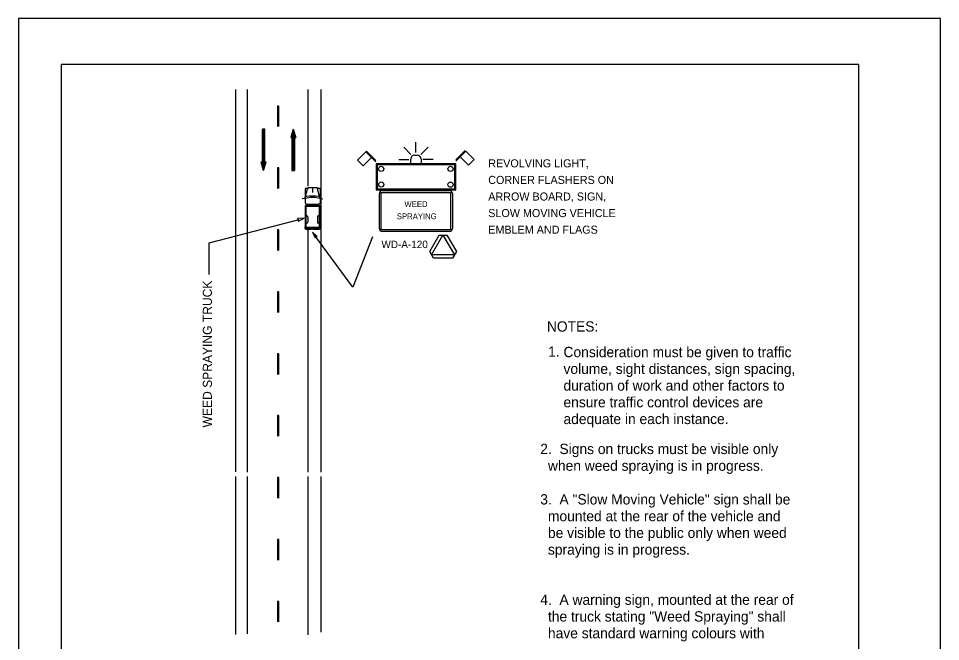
# Model space of a CAD drawing. Extents: x 1578 to 1794, y 169 to 448.
# Drawn here: x 1578.5 to 1794.5, y 301.9 to 448 of the extents above; entities that cross this region are included whole.
import ezdxf

# ---------------------------------------------------------------- set-up
doc = ezdxf.new("R2010")
doc.units = 0
for name, color, linetype in [('Level 1', 7, 'Continuous'), ('Level 10', 7, 'Continuous'), ('Level 2', 7, 'Continuous'), ('Level 44', 7, 'Continuous'), ('Level 60', 7, 'Continuous')]:
    doc.layers.add(name, color=color, linetype=linetype)

msp = doc.modelspace()

# ---------------------------------------------------------------- linework, layer by layer
at = {"layer": 'Level 1'}
for p, q in [((1646.51, 408.35), (1648.24, 408.35)), ((1647.37, 408.35), (1647.37, 407.24)), ((1645.6, 407.91), (1645.6, 404.82)), ((1645.66, 406.03), (1646.21, 408.09)), ((1645.9, 408.22), (1646.26, 408.22)), ((1648.49, 408.22), (1648.85, 408.22)), ((1649.07, 406.03), (1648.53, 408.09)), ((1649.14, 407.91), (1649.14, 404.82)), ((1645.6, 405.81), (1644.96, 405.74)), ((1645.6, 405.8), (1644.96, 405.72)), ((1645.6, 405.78), (1644.96, 405.7)), ((1645.6, 405.8), (1645.66, 406.03)), ((1645.6, 405.41), (1645.6, 405.41)), ((1645.6, 403.97), (1645.6, 399.15)), ((1645.82, 403.97), (1645.82, 399.15)), ((1645.9, 404.52), (1648.85, 404.52)), ((1645.9, 404.27), (1648.85, 404.27)), ((1645.9, 404.05), (1648.85, 404.05)), ((1648.92, 403.97), (1648.92, 399.15)), ((1649.14, 405.8), (1649.08, 406.03)), ((1649.14, 405.81), (1649.79, 405.74)), ((1649.14, 405.8), (1649.79, 405.72)), ((1649.14, 405.78), (1649.79, 405.7)), ((1649.14, 403.97), (1649.14, 399.15)), ((1645.82, 401.76), (1646.02, 401.76)), ((1648.92, 401.76), (1648.72, 401.76)), ((1645.82, 400.02), (1646.02, 400.02)), ((1646.26, 401.53), (1646.26, 400.25)), ((1648.49, 401.53), (1648.49, 400.25)), ((1648.92, 400.02), (1648.72, 400.02)), ((1645.54, 399.15), (1645.54, 398.89)), ((1645.83, 398.6), (1647.15, 398.6)), ((1645.9, 399.08), (1648.85, 399.08)), ((1645.9, 398.86), (1648.85, 398.86)), ((1647.6, 398.6), (1648.92, 398.6)), ((1649.21, 399.15), (1649.21, 398.89)), ((1674.8, 393.42), (1677, 397.23)), ((1675.26, 392.62), (1677.92, 397.23)), ((1677, 397.23), (1678.85, 397.23)), ((1677.92, 397.23), (1680.59, 392.62)), ((1678.85, 397.23), (1681.05, 393.42)), ((1675.72, 391.82), (1674.8, 393.42)), ((1681.05, 393.42), (1680.13, 391.82)), ((1680.59, 392.62), (1675.26, 392.62)), ((1680.13, 391.82), (1675.72, 391.82))]:
    msp.add_line(p, q, dxfattribs=at)
for centre, radius, start, end in [((1646.51, 408.05), 0.297, 90, 172.554), ((1648.24, 408.05), 0.297, 7.446, 90), ((1645.9, 407.92), 0.297, 90, 180), ((1645.95, 405.96), 0.297, 101.1133, 164.8989), ((1647.37, 398.73), 7.66, 78.8894, 101.1106), ((1648.85, 407.92), 0.297, 0, 90), ((1648.79, 405.96), 0.297, 14.8586, 78.8916), ((1647.37, 398.73), 7.29, 75.9432, 104.0544), ((1645.9, 404.82), 0.297, 180, 270), ((1645.9, 403.97), 0.297, 90, 180), ((1645.9, 403.97), 0.0766, 90, 180), ((1648.85, 404.82), 0.297, 270, 360), ((1648.85, 403.97), 0.297, 360, 90), ((1648.85, 403.97), 0.0766, 360, 90), ((1645.9, 399.15), 0.297, 180, 270), ((1645.9, 399.15), 0.0766, 180, 270), ((1648.85, 399.15), 0.297, 270, 360), ((1648.85, 399.15), 0.0766, 270, 360)]:
    msp.add_arc(centre, radius, start, end, dxfattribs=at)
at = {"layer": 'Level 10'}
for p, q in [((1629.33, 431.35), (1629.33, 341.73)), ((1632.06, 431.35), (1632.06, 341.68)), ((1646.28, 431.35), (1646.28, 408.73)), ((1649.3, 431.35), (1649.3, 341.62)), ((1635.62, 414.3), (1635.62, 422.05)), ((1636.2, 422.05), (1635.62, 422.05)), ((1635.62, 413.34), (1635.62, 422.05)), ((1635.69, 413.1), (1635.69, 422.05)), ((1635.77, 412.85), (1635.77, 422.05)), ((1635.84, 412.61), (1635.84, 422.05)), ((1635.91, 412.37), (1635.91, 422.05)), ((1635.98, 412.61), (1635.98, 422.05)), ((1636.06, 412.85), (1636.06, 422.05)), ((1636.13, 413.1), (1636.13, 422.05)), ((1636.2, 414.3), (1636.2, 422.05)), ((1636.2, 413.34), (1636.2, 422.05)), ((1642.84, 422.06), (1642.26, 420.13)), ((1642.62, 421.34), (1642.62, 412.39)), ((1642.7, 421.58), (1642.7, 412.39)), ((1642.77, 421.82), (1642.77, 412.39)), ((1642.84, 422.06), (1642.84, 412.39)), ((1642.84, 422.06), (1643.42, 420.13)), ((1642.91, 421.82), (1642.91, 412.39)), ((1642.99, 421.58), (1642.99, 412.39)), ((1643.06, 421.34), (1643.06, 412.39)), ((1642.26, 420.13), (1642.55, 420.13)), ((1642.33, 420.37), (1642.33, 420.13)), ((1642.41, 420.61), (1642.41, 420.13)), ((1642.48, 420.85), (1642.48, 420.13)), ((1642.55, 421.09), (1642.55, 412.39)), ((1642.55, 420.13), (1642.55, 412.39)), ((1643.13, 421.09), (1643.13, 412.39)), ((1643.13, 420.13), (1643.13, 412.39)), ((1643.13, 420.13), (1643.42, 420.13)), ((1643.2, 420.85), (1643.2, 420.13)), ((1643.28, 420.61), (1643.28, 420.13)), ((1643.35, 420.37), (1643.35, 420.13)), ((1660.03, 416.91), (1659.88, 416.75)), ((1670.42, 416.13), (1668.74, 417.81)), ((1671.58, 416.61), (1671.58, 418.99)), ((1672.74, 416.13), (1674.42, 417.81)), ((1681.93, 415.59), (1683.24, 416.9)), ((1683.24, 416.9), (1685.21, 414.93)), ((1659.88, 416.75), (1657.91, 414.78)), ((1657.91, 414.78), (1659.22, 413.47)), ((1659.22, 413.47), (1661.19, 415.44)), ((1661.19, 415.44), (1659.88, 416.75)), ((1661.19, 415.44), (1661.19, 415.44)), ((1667.56, 414.97), (1669.94, 414.97)), ((1670.37, 413.96), (1670.37, 415.05)), ((1671.3, 415.98), (1671.86, 415.98)), ((1671.56, 415.98), (1671.58, 415.98)), ((1672.79, 415.05), (1672.79, 413.96)), ((1675.6, 414.97), (1673.23, 414.97)), ((1683.9, 413.62), (1681.93, 415.59)), ((1681.93, 415.59), (1681.93, 415.59)), ((1685.21, 414.93), (1683.9, 413.62)), ((1635.91, 412.37), (1635.33, 414.3)), ((1635.62, 414.3), (1635.33, 414.3)), ((1635.4, 414.06), (1635.4, 414.3)), ((1635.48, 413.82), (1635.48, 414.3)), ((1635.55, 413.58), (1635.55, 414.3)), ((1635.91, 412.37), (1636.49, 414.3)), ((1636.49, 414.3), (1636.2, 414.3)), ((1636.28, 413.58), (1636.28, 414.3)), ((1636.35, 413.82), (1636.35, 414.3)), ((1636.42, 414.06), (1636.42, 414.3)), ((1672.79, 413.96), (1670.37, 413.96)), ((1642.55, 412.39), (1643.13, 412.39)), ((1663.02, 398.8), (1663.02, 406.97)), ((1663.71, 407.67), (1679.42, 407.67)), ((1671.57, 407.67), (1671.57, 407.67)), ((1680.12, 406.97), (1680.12, 398.8)), ((1645.54, 399.15), (1645.6, 399.15)), ((1646.28, 398.6), (1646.28, 341.62)), ((1649.21, 399.15), (1649.14, 399.15)), ((1679.42, 398.1), (1663.71, 398.1)), ((1629.33, 340.65), (1629.33, 303.63)), ((1632.06, 340.65), (1632.06, 303.75)), ((1646.28, 340.65), (1646.28, 303.5)), ((1649.3, 340.65), (1649.3, 304.12))]:
    msp.add_line(p, q, dxfattribs=at)
msp.add_lwpolyline([(1663.45, 407.2), (1679.67, 407.2), (1679.67, 398.46), (1663.45, 398.46)], close=True, dxfattribs=at)
for points in [[(1623.17, 387.99), (1623.17, 395.39), (1644.23, 400.91)], [(1661.42, 396.82), (1656.81, 385), (1647.89, 397.12)]]:
    msp.add_lwpolyline(points, dxfattribs=at)
for centre, radius in [((1663.46, 412.76), 0.609), ((1679.7, 412.76), 0.609), ((1663.46, 409.09), 0.609), ((1679.7, 409.05), 0.609), ((1647.37, 398.64), 0.0581)]:
    msp.add_circle(centre, radius, dxfattribs=at)
for centre, radius, start, end in [((1671.3, 415.05), 0.929, 90, 180), ((1671.86, 415.05), 0.929, 0, 90), ((1663.71, 406.97), 0.697, 90, 180), ((1679.42, 406.97), 0.697, 0, 90), ((1646.02, 401.53), 0.232, 0, 90), ((1648.72, 401.53), 0.232, 90, 180), ((1646.02, 400.25), 0.232, 270, 0), ((1648.72, 400.25), 0.232, 180, 270), ((1645.83, 398.89), 0.29, 180, 270), ((1647.37, 398.64), 0.174, 29.9957, 149.9771), ((1648.92, 398.89), 0.29, 270, 0), ((1663.71, 398.8), 0.697, 180, 270), ((1679.42, 398.8), 0.697, 270, 0)]:
    msp.add_arc(centre, radius, start, end, dxfattribs=at)
at = {"layer": 'Level 2'}
for p, q in [((1639.15, 427.49), (1639.15, 422.65)), ((1639.44, 427.49), (1639.15, 427.49)), ((1639.44, 422.65), (1639.44, 427.49)), ((1639.15, 412.97), (1639.15, 408.13)), ((1639.44, 412.97), (1639.15, 412.97)), ((1639.44, 408.13), (1639.44, 412.97)), ((1639.15, 398.46), (1639.15, 393.62)), ((1639.44, 398.46), (1639.15, 398.46)), ((1639.44, 393.62), (1639.44, 398.46)), ((1639.15, 383.94), (1639.15, 379.11)), ((1639.44, 383.94), (1639.15, 383.94)), ((1639.44, 379.11), (1639.44, 383.94)), ((1639.15, 369.43), (1639.15, 364.59)), ((1639.44, 369.43), (1639.15, 369.43)), ((1639.44, 364.59), (1639.44, 369.43)), ((1639.15, 354.92), (1639.15, 350.08)), ((1639.44, 354.92), (1639.15, 354.92)), ((1639.44, 350.08), (1639.44, 354.92)), ((1639.15, 340.4), (1639.15, 335.56)), ((1639.44, 340.4), (1639.15, 340.4)), ((1639.44, 335.56), (1639.44, 340.4)), ((1639.15, 325.89), (1639.15, 321.05)), ((1639.44, 325.89), (1639.15, 325.89)), ((1639.44, 321.05), (1639.44, 325.89)), ((1639.15, 311.37), (1639.15, 306.54)), ((1639.44, 311.37), (1639.15, 311.37)), ((1639.44, 306.54), (1639.44, 311.37))]:
    msp.add_line(p, q, dxfattribs=at)
at = {"layer": 'Level 44'}
for p, q in [((1662.2, 414.74), (1660.03, 416.91)), ((1680.92, 414.89), (1683.09, 417.06)), ((1662.2, 414.43), (1661.19, 415.44)), ((1680.92, 414.58), (1681.93, 415.59)), ((1680.92, 413.96), (1662.25, 413.96)), ((1662.25, 413.96), (1662.25, 407.83)), ((1662.52, 413.68), (1662.52, 408.1)), ((1680.64, 413.68), (1662.53, 413.68)), ((1662.53, 413.68), (1662.53, 408.1)), ((1680.64, 413.68), (1680.64, 408.1)), ((1680.92, 407.83), (1680.92, 413.96)), ((1662.25, 407.83), (1680.92, 407.83)), ((1662.53, 408.1), (1680.64, 408.1))]:
    msp.add_line(p, q, dxfattribs=at)
at = {"layer": 'Level 60'}
msp.add_line((1794.47, 448.02), (1794.47, 448.02), dxfattribs=at)
for points in [[(1794.47, 448.02), (1578.47, 448.02), (1578.47, 169.02), (1794.47, 169.02)], [(1775.35, 437.21), (1588.47, 437.21), (1588.47, 179.83), (1775.35, 179.83)], [(1644, 400.53), (1645.37, 401.2), (1643.85, 401.11), (1644.02, 400.84)], [(1648.47, 396.92), (1647.34, 397.95), (1647.98, 396.57), (1648.17, 396.83)]]:
    msp.add_lwpolyline(points, close=True, dxfattribs=at)

# ---------------------------------------------------------------- texts
at = {"layer": 'Level 10'}
for s, height, p in [('REVOLVING LIGHT,', 1.887, (1688.52, 413.11)), ('CORNER FLASHERS ON', 1.887, (1688.52, 409.22)), ('ARROW BOARD, SIGN,', 1.887, (1688.52, 405.33)), ('WEED', 1.35, (1668.89, 403.81)), ('SPRAYING', 1.35, (1667.11, 400.96)), ('SLOW MOVING VEHICLE', 1.887, (1688.52, 401.45)), ('EMBLEM AND FLAGS', 1.887, (1688.52, 397.56)), ('NOTES:', 2.419, (1702.26, 374.6)), ('1.', 2.419, (1702.55, 368.72)), ('Consideration must be given to traffic ', 2.419, (1706.15, 368.61)), ('volume, sight distances, sign spacing, ', 2.419, (1706.15, 364.69)), ('duration of work and other factors to ', 2.419, (1706.15, 360.77)), ('ensure traffic control devices are ', 2.419, (1706.15, 356.85)), ('adequate in each instance.', 2.419, (1706.15, 352.93)), ('2.  Signs on trucks must be visible only ', 2.419, (1700.71, 345.9)), ('  when weed spraying is in progress.', 2.419, (1700.71, 341.98)), ('3.  A "Slow Moving Vehicle" sign shall be', 2.419, (1700.71, 334.08)), ('  mounted at the rear of the vehicle and', 2.419, (1700.71, 330.16)), ('  be visible to the public only when weed', 2.419, (1700.71, 326.24)), ('  spraying is in progress.', 2.419, (1700.71, 322.32)), ('4.  A warning sign, mounted at the rear of ', 2.419, (1700.71, 310.56)), ('  the truck stating "Weed Spraying" shall ', 2.419, (1700.71, 306.64)), ('  have standard warning colours with', 2.419, (1700.71, 302.72))]:
    msp.add_text(s, height=height, dxfattribs=at).set_placement(p)
for s, height, rotation, p in [('WD-A-120', 1.742, 360, (1663.5, 394.18)), ('WEED SPRAYING TRUCK', 2.115, 90, (1623.78, 352.15))]:
    msp.add_text(s, height=height, rotation=rotation, dxfattribs=at).set_placement(p)

doc.saveas('drawing.dxf')
